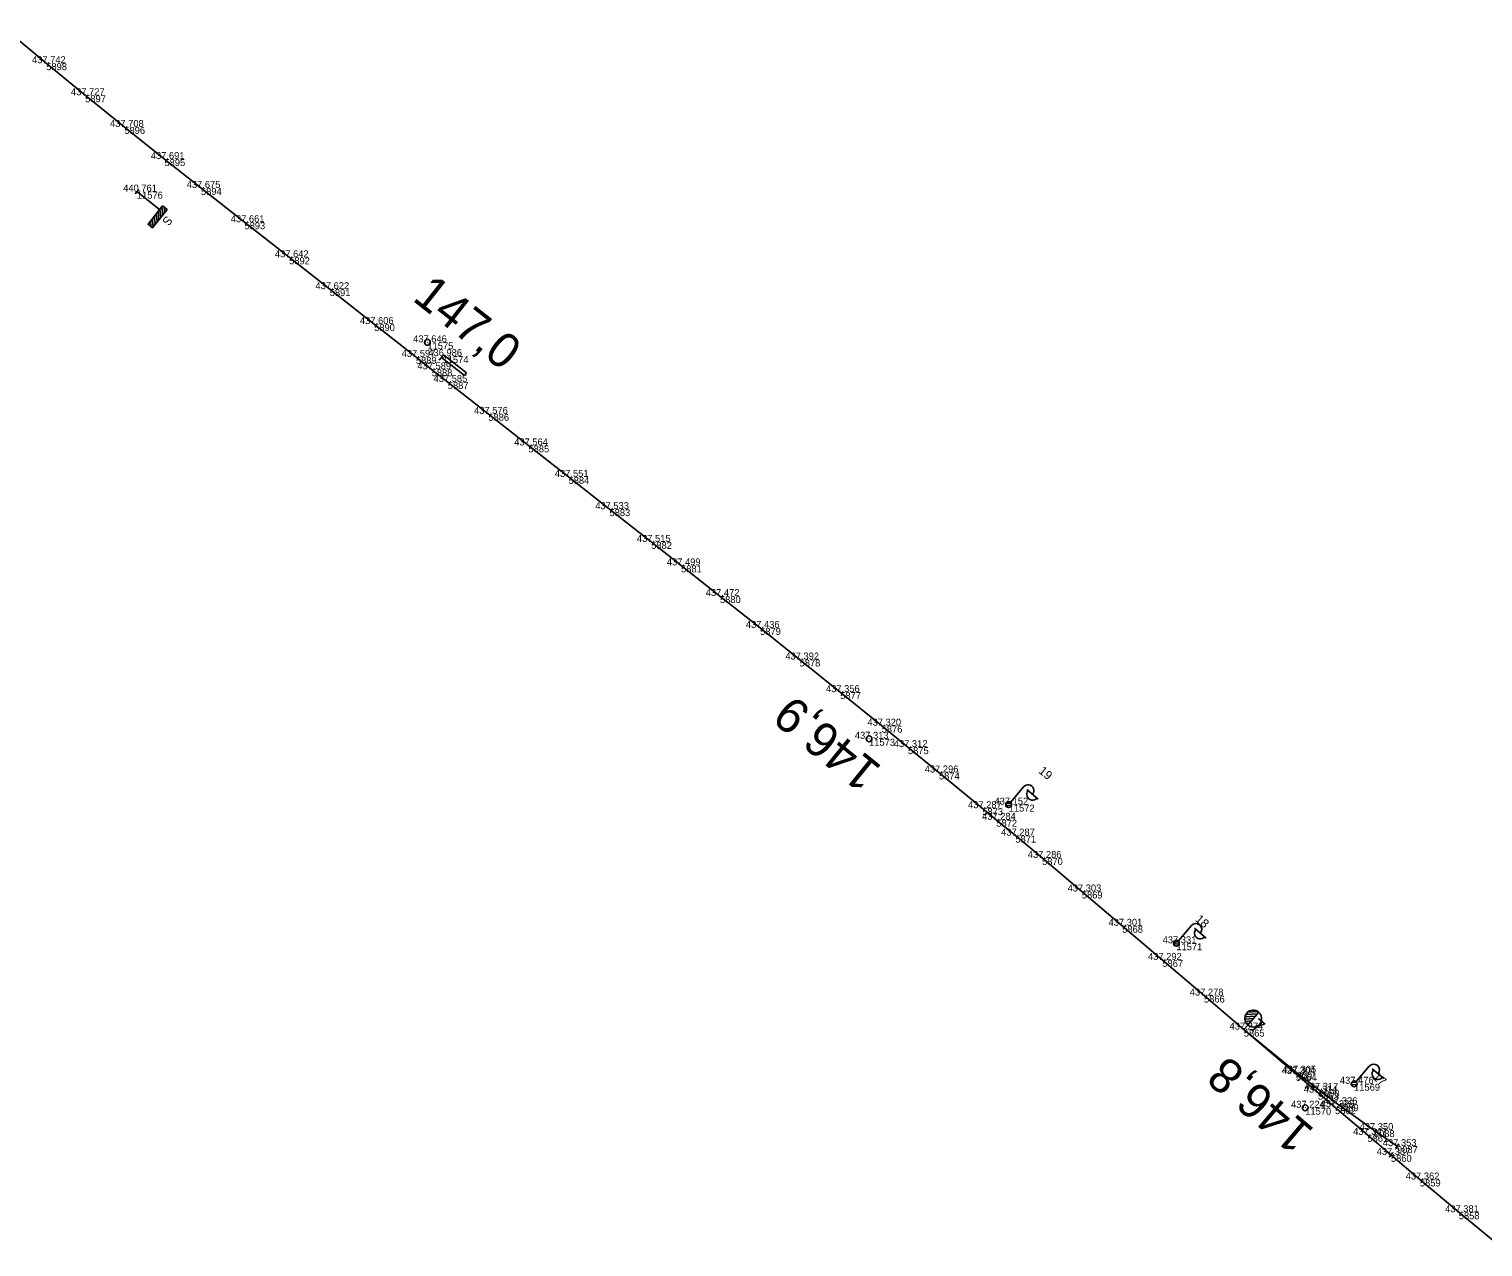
# Model space of a CAD drawing. Extents: x -654154 to -652650, y -1166925 to -1164904.
# Drawn here: x -653646.5 to -653396.2, y -1165715.5 to -1165505.8 of the extents above; entities that cross this region are included whole.
import ezdxf

# ---------------------------------------------------------------- set-up
doc = ezdxf.new("R2010")
doc.units = 0
for name, color, linetype in [('Vrstva 1', 7, 'Continuous'), ('Vrstva 2', 7, 'Continuous'), ('Vrstva 25', 7, 'Continuous'), ('Vrstva 6', 7, 'Continuous'), ('Vrstva 60', 7, 'Continuous'), ('Vrstva 61', 7, 'Continuous'), ('Vrstva 7', 7, 'Continuous'), ('Vrstva 9', 7, 'Continuous')]:
    doc.layers.add(name, color=color, linetype=linetype)

msp = doc.modelspace()

# ---------------------------------------------------------------- linework, layer by layer
at = {"layer": 'Vrstva 1'}
msp.add_lwpolyline([(-653393.1, -1165715.51), (-653400.32, -1165709.54), (-653407.01, -1165703.9), (-653412, -1165699.67), (-653416.05, -1165696.22), (-653421.63, -1165691.45), (-653424.56, -1165688.95), (-653428.37, -1165685.72), (-653437.33, -1165678.1), (-653444.18, -1165672.23), (-653451.36, -1165666.1), (-653458.26, -1165660.22), (-653465.21, -1165654.31), (-653472.06, -1165648.53), (-653476.66, -1165644.69), (-653479.94, -1165641.96), (-653482.35, -1165639.97), (-653489.81, -1165633.82), (-653495.15, -1165629.46), (-653499.68, -1165625.76), (-653506.81, -1165619.99), (-653513.8, -1165614.37), (-653520.6, -1165608.93), (-653527.51, -1165603.45), (-653534.21, -1165598.17), (-653539.35, -1165594.12), (-653546.53, -1165588.48), (-653553.58, -1165582.93), (-653560.48, -1165577.51), (-653567.39, -1165572.07), (-653574.37, -1165566.59), (-653577.15, -1165564.41), (-653579.86, -1165562.27), (-653587.05, -1165556.61), (-653594.7, -1165550.6), (-653601.68, -1165545.12), (-653609.37, -1165539.08), (-653616.86, -1165533.18), (-653623.14, -1165528.21), (-653630.06, -1165522.67), (-653636.8, -1165517.22), (-653643.5, -1165511.7), (-653650.49, -1165505.82)], dxfattribs=at)
at = {"layer": 'Vrstva 2'}
for p, q in [((-653437.14, -1165675.91), (-653435.34, -1165675.76)), ((-653437, -1165675.51), (-653434.99, -1165675.35)), ((-653436.68, -1165675.11), (-653434.92, -1165674.96)), ((-653434.76, -1165675.08), (-653436.66, -1165677.31)), ((-653434.76, -1165675.08), (-653434.76, -1165675.08)), ((-653436.66, -1165677.31), (-653437.33, -1165678.1)), ((-653437.16, -1165676.29), (-653435.69, -1165676.17)), ((-653437.09, -1165676.67), (-653436.03, -1165676.58)), ((-653436.9, -1165677.03), (-653436.38, -1165676.99)), ((-653410.66, -1165697.75), (-653411.23, -1165698.57)), ((-653412.33, -1165700.05), (-653411.68, -1165699.28))]:
    msp.add_line(p, q, dxfattribs=at)
for points in [[(-653412, -1165699.67), (-653416.05, -1165696.22), (-653421.63, -1165691.45), (-653424.56, -1165688.95), (-653428.37, -1165685.72), (-653437.33, -1165678.1)], [(-653410.95, -1165698.16), (-653414.94, -1165695.4), (-653421.13, -1165690.94), (-653424.42, -1165688.46), (-653428.22, -1165685.52), (-653437.33, -1165678.1)]]:
    msp.add_lwpolyline(points, dxfattribs=at)
for centre, start, end in [((-653435.71, -1165676.19), 49.6562, 229.617), ((-653435.71, -1165676.2), 229.5666, 50.0361)]:
    msp.add_arc(centre, 1.46, start, end, dxfattribs=at)
at = {"layer": 'Vrstva 25'}
for p, q in [((-653477.48, -1165638.97), (-653475.24, -1165636.29)), ((-653474.7, -1165636.74), (-653472.71, -1165638.41)), ((-653478.27, -1165639.16), (-653477.39, -1165639.08)), ((-653478.27, -1165639.54), (-653477.32, -1165639.45)), ((-653448.61, -1165662.85), (-653446.34, -1165660.18)), ((-653445.81, -1165660.64), (-653443.83, -1165662.33)), ((-653449.4, -1165663.03), (-653448.52, -1165662.96)), ((-653449.4, -1165663.4), (-653448.45, -1165663.33)), ((-653418.01, -1165687.04), (-653415.74, -1165684.38)), ((-653415.21, -1165684.83), (-653413.23, -1165686.52)), ((-653418.8, -1165687.22), (-653417.92, -1165687.15)), ((-653418.8, -1165687.6), (-653417.85, -1165687.52))]:
    msp.add_line(p, q, dxfattribs=at)
for centre in [(-653477.81, -1165639.36), (-653448.94, -1165663.23), (-653418.34, -1165687.42)]:
    msp.add_circle(centre, 0.5, dxfattribs=at)
for centre, start, end in [((-653474.47, -1165636.93), 320.0757, 140.0757), ((-653473.71, -1165637.58), 139.3731, 320.7783), ((-653445.58, -1165660.83), 319.5007, 139.5007), ((-653444.83, -1165661.49), 138.7981, 320.2033), ((-653414.98, -1165685.03), 319.5138, 139.5138), ((-653414.23, -1165685.69), 138.8113, 320.2164)]:
    msp.add_arc(centre, 1, start, end, dxfattribs=at)
at = {"layer": 'Vrstva 6'}
for p, q in [((-653627.58, -1165533.42), (-653628.2, -1165534.21)), ((-653627.89, -1165533.81), (-653623.98, -1165536.91)), ((-653624.75, -1165539.48), (-653624.91, -1165538.08)), ((-653624.42, -1165539.07), (-653624.59, -1165537.66)), ((-653624.09, -1165538.65), (-653624.25, -1165537.25)), ((-653623.76, -1165538.24), (-653623.93, -1165536.83)), ((-653623.43, -1165537.82), (-653623.6, -1165536.42)), ((-653623.1, -1165537.4), (-653623.21, -1165536.5)), ((-653625.47, -1165539.81), (-653625.57, -1165538.91)), ((-653625.08, -1165539.9), (-653625.24, -1165538.5))]:
    msp.add_line(p, q, dxfattribs=at)
msp.add_lwpolyline([(-653623.49, -1165536.28), (-653622.7, -1165536.9), (-653625.19, -1165540.04), (-653625.97, -1165539.42)], close=True, dxfattribs=at)
at = {"layer": 'Vrstva 60'}
for p, q in [((-653643.5, -1165511.7), (-653643.5, -1165511.7)), ((-653636.8, -1165517.22), (-653636.8, -1165517.22)), ((-653630.06, -1165522.67), (-653630.06, -1165522.67)), ((-653623.14, -1165528.21), (-653623.14, -1165528.21)), ((-653616.86, -1165533.18), (-653616.86, -1165533.18)), ((-653627.89, -1165533.81), (-653627.89, -1165533.81)), ((-653609.37, -1165539.08), (-653609.37, -1165539.08)), ((-653601.68, -1165545.12), (-653601.68, -1165545.12)), ((-653594.7, -1165550.6), (-653594.7, -1165550.6)), ((-653587.05, -1165556.61), (-653587.05, -1165556.61)), ((-653577.88, -1165559.76), (-653577.88, -1165559.76)), ((-653579.86, -1165562.27), (-653579.86, -1165562.27)), ((-653575.27, -1165562.14), (-653575.27, -1165562.14)), ((-653577.15, -1165564.41), (-653577.15, -1165564.41)), ((-653574.37, -1165566.59), (-653574.37, -1165566.59)), ((-653567.39, -1165572.07), (-653567.39, -1165572.07)), ((-653560.48, -1165577.51), (-653560.48, -1165577.51)), ((-653553.58, -1165582.93), (-653553.58, -1165582.93)), ((-653546.53, -1165588.48), (-653546.53, -1165588.48)), ((-653539.35, -1165594.12), (-653539.35, -1165594.12)), ((-653534.21, -1165598.17), (-653534.21, -1165598.17)), ((-653527.51, -1165603.45), (-653527.51, -1165603.45)), ((-653520.6, -1165608.93), (-653520.6, -1165608.93)), ((-653513.8, -1165614.37), (-653513.8, -1165614.37)), ((-653506.81, -1165619.99), (-653506.81, -1165619.99)), ((-653499.68, -1165625.76), (-653499.68, -1165625.76)), ((-653501.84, -1165628.02), (-653501.84, -1165628.02)), ((-653495.15, -1165629.46), (-653495.15, -1165629.46)), ((-653489.81, -1165633.82), (-653489.81, -1165633.82)), ((-653482.35, -1165639.97), (-653482.35, -1165639.97)), ((-653477.81, -1165639.36), (-653477.81, -1165639.36)), ((-653479.94, -1165641.96), (-653479.94, -1165641.96)), ((-653476.66, -1165644.69), (-653476.66, -1165644.69)), ((-653472.06, -1165648.53), (-653472.06, -1165648.53)), ((-653465.21, -1165654.31), (-653465.21, -1165654.31)), ((-653458.26, -1165660.22), (-653458.26, -1165660.22)), ((-653448.94, -1165663.23), (-653448.94, -1165663.23)), ((-653451.36, -1165666.1), (-653451.36, -1165666.1)), ((-653444.18, -1165672.23), (-653444.18, -1165672.23)), ((-653437.33, -1165678.1), (-653437.33, -1165678.1)), ((-653428.37, -1165685.72), (-653428.37, -1165685.72)), ((-653428.22, -1165685.52), (-653428.22, -1165685.52)), ((-653418.34, -1165687.42), (-653418.34, -1165687.42)), ((-653424.56, -1165688.95), (-653424.56, -1165688.95)), ((-653424.42, -1165688.46), (-653424.42, -1165688.46)), ((-653426.75, -1165691.55), (-653426.75, -1165691.55)), ((-653421.63, -1165691.45), (-653421.63, -1165691.45)), ((-653421.13, -1165690.94), (-653421.13, -1165690.94)), ((-653414.94, -1165695.4), (-653414.94, -1165695.4)), ((-653416.05, -1165696.22), (-653416.05, -1165696.22)), ((-653410.95, -1165698.16), (-653410.95, -1165698.16)), ((-653412, -1165699.67), (-653412, -1165699.67)), ((-653407.01, -1165703.9), (-653407.01, -1165703.9)), ((-653400.32, -1165709.54), (-653400.32, -1165709.54))]:
    msp.add_line(p, q, dxfattribs=at)
at = {"layer": 'Vrstva 7'}
for p, q in [((-653577.92, -1165559.73), (-653577.84, -1165559.79)), ((-653501.8, -1165628.05), (-653501.88, -1165627.99)), ((-653426.71, -1165691.58), (-653426.79, -1165691.51))]:
    msp.add_line(p, q, dxfattribs=at)
for centre in [(-653577.88, -1165559.76), (-653501.84, -1165628.02), (-653426.75, -1165691.55)]:
    msp.add_circle(centre, 0.5, dxfattribs=at)
at = {"layer": 'Vrstva 9'}
for p, q in [((-653575.45, -1165562.38), (-653575.83, -1165562.85)), ((-653575.08, -1165561.91), (-653575.45, -1165562.38)), ((-653575.45, -1165562.38), (-653571.52, -1165565.47)), ((-653571.15, -1165565), (-653575.08, -1165561.91)), ((-653571.52, -1165565.47), (-653571.15, -1165565))]:
    msp.add_line(p, q, dxfattribs=at)

# ---------------------------------------------------------------- texts
at = {"layer": 'Vrstva 2'}
msp.add_text('7', height=2.5, rotation=319.6366, dxfattribs=at).set_placement((-653436.47, -1165677.88))
at = {"layer": 'Vrstva 25'}
for s, rotation, p in [('19', 320.0757, (-653472.78, -1165633.77)), ('18', 319.5007, (-653445.81, -1165659.28)), ('17', 319.5138, (-653415.28, -1165686.45))]:
    msp.add_text(s, height=1.5, rotation=rotation, dxfattribs=at).set_placement(p)
at = {"layer": 'Vrstva 6'}
msp.add_text('S', height=1.5, rotation=231.6339, dxfattribs=at).set_placement((-653622.79, -1165537.85))
at = {"layer": 'Vrstva 60'}
for s, p in [('5898', (-653643.5, -1165512.9)), ('5897', (-653636.8, -1165518.42)), ('5896', (-653630.06, -1165523.87)), ('5895', (-653623.14, -1165529.41)), ('5894', (-653616.86, -1165534.38)), ('11576', (-653627.89, -1165535.02)), ('5893', (-653609.37, -1165540.28)), ('5892', (-653601.68, -1165546.32)), ('5891', (-653594.7, -1165551.8)), ('5890', (-653587.05, -1165557.81)), ('11575', (-653577.88, -1165560.96)), ('5889', (-653579.86, -1165563.47)), ('11574', (-653575.27, -1165563.34)), ('5888', (-653577.15, -1165565.6)), ('5887', (-653574.37, -1165567.79)), ('5886', (-653567.39, -1165573.27)), ('5885', (-653560.48, -1165578.71)), ('5884', (-653553.58, -1165584.13)), ('5883', (-653546.53, -1165589.68)), ('5882', (-653539.35, -1165595.32)), ('5881', (-653534.21, -1165599.37)), ('5880', (-653527.51, -1165604.65)), ('5879', (-653520.6, -1165610.13)), ('5878', (-653513.8, -1165615.57)), ('5877', (-653506.81, -1165621.19)), ('5876', (-653499.68, -1165626.96)), ('11573', (-653501.84, -1165629.22)), ('5875', (-653495.15, -1165630.66)), ('5874', (-653489.81, -1165635.02)), ('5873', (-653482.35, -1165641.17)), ('11572', (-653477.81, -1165640.56)), ('5872', (-653479.94, -1165643.16)), ('5871', (-653476.66, -1165645.89)), ('5870', (-653472.06, -1165649.74)), ('5869', (-653465.21, -1165655.51)), ('5868', (-653458.26, -1165661.42)), ('11571', (-653448.94, -1165664.43)), ('5867', (-653451.36, -1165667.3)), ('5866', (-653444.18, -1165673.43)), ('5865', (-653437.33, -1165679.3)), ('5864', (-653428.37, -1165686.92)), ('9091', (-653428.22, -1165686.72)), ('11569', (-653418.34, -1165688.62)), ('5863', (-653424.56, -1165690.15)), ('9090', (-653424.42, -1165689.66)), ('11570', (-653426.75, -1165692.75)), ('5862', (-653421.63, -1165692.65)), ('9089', (-653421.13, -1165692.14)), ('9088', (-653414.94, -1165696.6)), ('5861', (-653416.05, -1165697.42)), ('9087', (-653410.95, -1165699.36)), ('5860', (-653412, -1165700.86)), ('5859', (-653407.01, -1165705.1)), ('5858', (-653400.32, -1165710.74))]:
    msp.add_text(s, height=1.2, dxfattribs=at).set_placement(p)
at = {"layer": 'Vrstva 61'}
for s, p in [('437.742', (-653645.95, -1165511.7)), ('437.727', (-653639.25, -1165517.22)), ('437.708', (-653632.52, -1165522.67)), ('437.691', (-653625.5, -1165528.21)), ('440.761', (-653630.25, -1165533.81)), ('437.675', (-653619.32, -1165533.18)), ('437.661', (-653611.73, -1165539.08)), ('437.642', (-653604.13, -1165545.12)), ('437.622', (-653597.15, -1165550.6)), ('437.606', (-653589.5, -1165556.61)), ('437.646', (-653580.34, -1165559.76)), ('437.597', (-653582.31, -1165562.27)), ('437.589', (-653579.6, -1165564.41)), ('436.986', (-653577.72, -1165562.14)), ('437.585', (-653576.82, -1165566.59)), ('437.576', (-653569.84, -1165572.07)), ('437.564', (-653562.93, -1165577.51)), ('437.551', (-653555.94, -1165582.93)), ('437.533', (-653548.98, -1165588.48)), ('437.515', (-653541.81, -1165594.12)), ('437.499', (-653536.66, -1165598.17)), ('437.472', (-653529.96, -1165603.45)), ('437.436', (-653523.05, -1165608.93)), ('437.392', (-653516.25, -1165614.37)), ('437.356', (-653509.26, -1165619.99)), ('437.320', (-653502.13, -1165625.76)), ('437.313', (-653504.29, -1165628.02)), ('437.312', (-653497.59, -1165629.46)), ('437.296', (-653492.26, -1165633.82)), ('437.152', (-653480.25, -1165639.36)), ('437.287', (-653484.8, -1165639.97)), ('437.284', (-653482.39, -1165641.96)), ('437.287', (-653479.11, -1165644.69)), ('437.286', (-653474.52, -1165648.53)), ('437.303', (-653467.66, -1165654.31)), ('437.301', (-653460.61, -1165660.22)), ('437.331', (-653451.3, -1165663.23)), ('437.292', (-653453.81, -1165666.1)), ('437.278', (-653446.63, -1165672.23)), ('437.274', (-653439.78, -1165678.1)), ('437.304', (-653430.82, -1165685.72)), ('437.305', (-653430.68, -1165685.52)), ('437.314', (-653427.01, -1165688.95)), ('437.317', (-653426.87, -1165688.46)), ('437.476', (-653420.79, -1165687.42)), ('437.224', (-653429.2, -1165691.55)), ('437.325', (-653424.09, -1165691.45)), ('437.326', (-653423.58, -1165690.94)), ('437.347', (-653418.5, -1165696.22)), ('437.350', (-653417.39, -1165695.4)), ('437.353', (-653413.4, -1165698.16)), ('437.337', (-653414.45, -1165699.67)), ('437.362', (-653409.46, -1165703.9)), ('437.381', (-653402.67, -1165709.54))]:
    msp.add_text(s, height=1.2, dxfattribs=at).set_placement(p)
at = {"layer": 'Vrstva 7'}
for s, rotation, p in [('147,0', 321.8094, (-653580.65, -1165552.43)), ('146,9', 140.8601, (-653499.42, -1165632.95)), ('146,8', 139.5424, (-653424.96, -1165695.38))]:
    msp.add_text(s, height=6, rotation=rotation, dxfattribs=at).set_placement(p)

doc.saveas('drawing.dxf')
